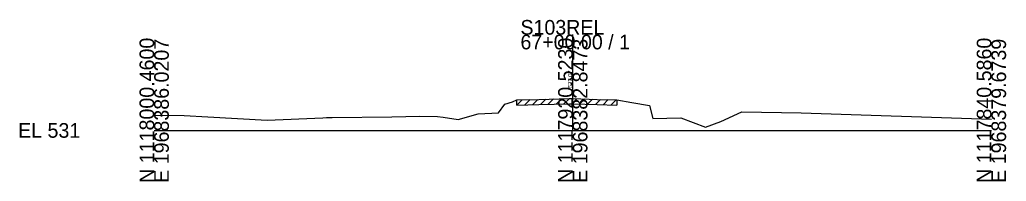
# Model space of a CAD drawing. Extents: x -26 to 163, y -10 to 24518.
# Drawn here: x -25.7 to 162.8, y 15490.3 to 15521.1 of the extents above; entities that cross this region are included whole.
import ezdxf

# ---------------------------------------------------------------- set-up
doc = ezdxf.new("R2010")
doc.units = 0
for name, color, linetype in [('RD_GPK_XS_Cell', 7, 'Continuous'), ('RD_XS_ExGround', 7, 'Continuous'), ('RD_XS_ExPaveRet', 7, 'Continuous'), ('RD_XS_TX_Elev_EX', 7, 'Continuous')]:
    doc.layers.add(name, color=color, linetype=linetype)

msp = doc.modelspace()

# ---------------------------------------------------------------- linework, layer by layer
at = {"layer": 'RD_GPK_XS_Cell'}
for p, q in [((80, 15500), (80, 15518.27)), ((0, 15500), (80, 15500)), ((80, 15500), (160, 15500))]:
    msp.add_line(p, q, dxfattribs=at)
at = {"layer": 'RD_XS_ExGround'}
msp.add_lwpolyline([(0, 15502.92), (5.74, 15502.84), (10.26, 15502.58), (21.6, 15501.96), (32.22, 15502.43), (32.92, 15502.46), (33.99, 15502.48), (45.43, 15502.62), (50.76, 15502.7), (54.16, 15502.66), (55.2, 15502.51), (58.12, 15502.09), (61.93, 15503.17), (65.82, 15503.34), (67.04, 15505.01), (68.46, 15505.46), (69.31, 15505.83), (73.48, 15505.93), (79.4, 15506.09), (80, 15506.07), (84.66, 15505.93), (88.39, 15505.83), (91.28, 15505.34), (94.63, 15504.74), (95.28, 15502.25), (100.62, 15502.42), (105.36, 15500.62), (108.32, 15501.73), (112.33, 15503.56), (123.62, 15503.36), (160, 15502.12)], dxfattribs=at)
at = {"layer": 'RD_XS_ExPaveRet'}
for p, q in [((69.31, 15504.83), (70.33, 15505.85)), ((69.31, 15504.83), (69.31, 15505.83)), ((69.31, 15504.83), (73.48, 15504.93)), ((70.81, 15504.86), (71.83, 15505.89)), ((72.31, 15504.9), (73.33, 15505.93)), ((73.48, 15504.93), (79.4, 15505.09)), ((73.81, 15504.94), (74.84, 15505.97)), ((75.31, 15504.98), (76.34, 15506.01)), ((76.81, 15505.02), (77.84, 15506.05)), ((78.31, 15505.06), (79.34, 15506.09)), ((79.4, 15505.09), (80, 15505.07)), ((79.81, 15505.08), (80.78, 15506.05)), ((80, 15505.07), (84.66, 15504.93)), ((81.31, 15505.03), (82.28, 15506)), ((82.81, 15504.99), (83.78, 15505.96)), ((84.31, 15504.94), (85.28, 15505.92)), ((84.66, 15504.93), (88.39, 15504.83)), ((85.81, 15504.9), (86.78, 15505.87)), ((87.31, 15504.86), (88.28, 15505.83)), ((88.39, 15505.83), (88.39, 15504.83))]:
    msp.add_line(p, q, dxfattribs=at)

# ---------------------------------------------------------------- texts
at = {"layer": 'RD_GPK_XS_Cell'}
for s, p in [('S103REL', (70, 15518.27)), ('67+00.00 / 1', (70, 15515.47)), ('EL 531', (-26, 15498.6))]:
    msp.add_text(s, height=2.8, dxfattribs=at).set_placement(p)
for s, p in [('N 1118000.4600', (0, 15490)), ('E 1968386.0207', (2.8, 15490)), ('N 1117920.5230', (80, 15490)), ('E 1968382.8473', (82.8, 15490)), ('N 1117840.5860', (160, 15490)), ('E 1968379.6739', (162.8, 15490))]:
    msp.add_text(s, height=2.8, rotation=90, dxfattribs=at).set_placement(p)
at = {"layer": 'RD_XS_TX_Elev_EX'}
msp.add_text('537.07', height=0.8, rotation=90, dxfattribs=at).set_placement((79.9, 15508.07))

doc.saveas('drawing.dxf')
